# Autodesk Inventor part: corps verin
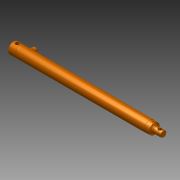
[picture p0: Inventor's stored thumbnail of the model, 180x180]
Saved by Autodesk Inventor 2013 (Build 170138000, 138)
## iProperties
Created: 2015-07
Part Number: corps verin
Material: Générique
Document SubType Name: Modeling
Designer: OL
Density: 1 g/cm^3
Norme de conversion: STEP AP203
Nom du fichier: 630.5.STEP
Préprocesseur: SolidWorks 2013
Postprocesseur: Build: 138, Release: 2013 RTM - Date: Thu 03/01/2012
Unités envoyées: millimètre
Incertitude: 1e-05
Author: OL
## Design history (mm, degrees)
node "630.51"
feature "Composite1"
body "Srf1"
